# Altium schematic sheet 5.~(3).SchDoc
size 420 x 297 mm
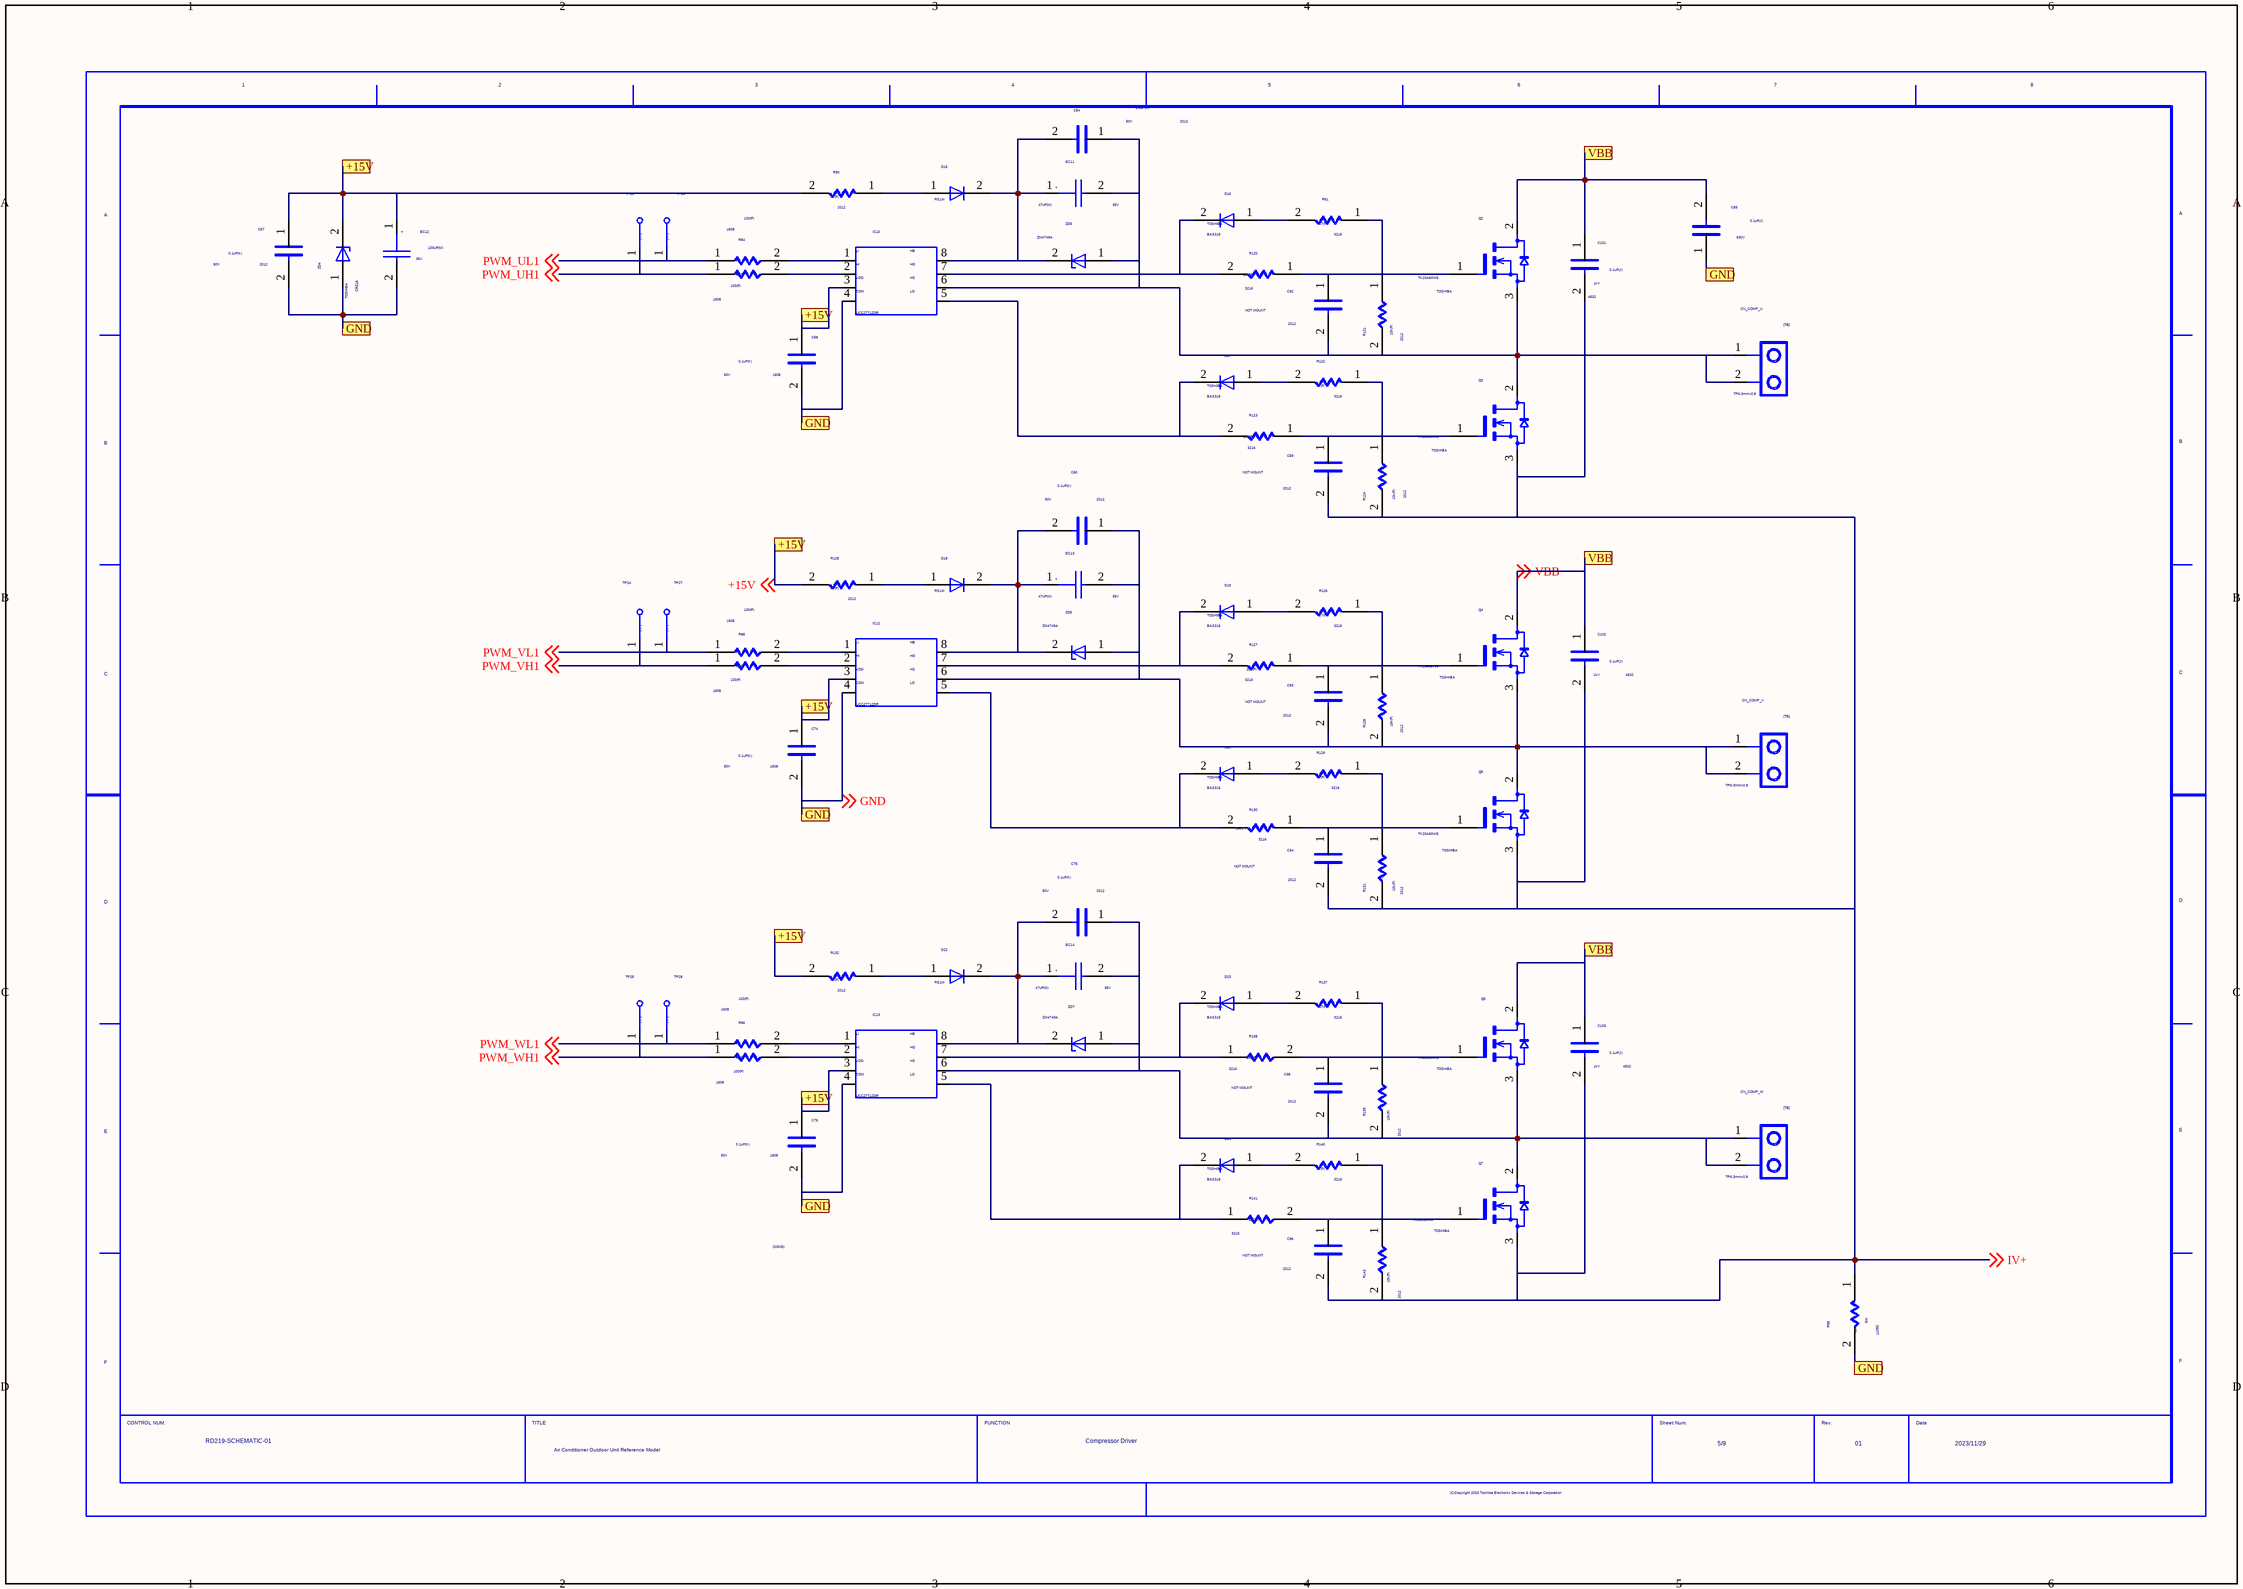
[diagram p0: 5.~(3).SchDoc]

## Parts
C54  VAL2: 50V  SIZECODESMD: 2012  VAL1: 0.1uF(K)  (hidden comment: C)
C55  VAL2: 630V  VAL1: 0.1uF(J)  (hidden comment: C)
C57  SIZECODESMD: 2012  VAL2: 50V  VAL1: 0.1uF(K)  (hidden comment: C)
C58  VAL2: 50V  SIZECODESMD: 1608  VAL1: 0.1uF(K)  (hidden comment: C)
C59  SIZECODESMD: 2012  NOTMOUNT: NOT MOUNT  (hidden comment: C)
C60  VAL2: 50V  SIZECODESMD: 2012  VAL1: 0.1uF(K)  (hidden comment: C)
C74  VAL2: 50V  SIZECODESMD: 1608  VAL1: 0.1uF(K)  (hidden comment: C)
C75  VAL2: 50V  SIZECODESMD: 2012  VAL1: 0.1uF(K)  (hidden comment: C)
C76  COMPCOMMENT: (SGND)  VAL2: 50V  SIZECODESMD: 1608  VAL1: 0.1uF(K)  (hidden comment: C)
C92  NOTMOUNT: NOT MOUNT  SIZECODESMD: 2012  (hidden comment: C)
C93  NOTMOUNT: NOT MOUNT  SIZECODESMD: 2012  (hidden comment: C)
C94  SIZECODESMD: 2012  NOTMOUNT: NOT MOUNT  (hidden comment: C)
C95  NOTMOUNT: NOT MOUNT  SIZECODESMD: 2012  (hidden comment: C)
C96  SIZECODESMD: 2012  NOTMOUNT: NOT MOUNT  (hidden comment: C)
C101  VAL2: 1kV  SIZECODESMD: 4532  VAL1: 0.1uF(J)  (hidden comment: C)
C102  VAL2: 1kV  SIZECODESMD: 4532  VAL1: 0.1uF(J)  (hidden comment: C)
C103  VAL2: 1kV  SIZECODESMD: 4532  VAL1: 0.1uF(J)  (hidden comment: C)
CN_COMP_U  COMPCOMMENT: TP6.3mmx0.8  (hidden comment: TB2A)
CN_COMP_V  COMPCOMMENT: TP6.3mmx0.8  (hidden comment: TB2A)
CN_COMP_W  COMPCOMMENT: TP6.3mmx0.8  (hidden comment: TB2A)
D15  VAL3: RS1M  (hidden comment: D_CUSTOM)
D16  USERCOMPTEXT3: TOSHIBA  VAL3: BAS316  (hidden comment: D_CUSTOM)
D17  USERCOMPTEXT3: TOSHIBA  VAL3: BAS316  (hidden comment: D_CUSTOM)
D18  VAL3: RS1M  (hidden comment: D_CUSTOM)
D19  USERCOMPTEXT3: TOSHIBA  VAL3: BAS316  (hidden comment: D_CUSTOM)
D21  USERCOMPTEXT3: TOSHIBA  VAL3: BAS316  (hidden comment: D_CUSTOM)
D22  VAL3: RS1M  (hidden comment: D_CUSTOM)
D23  USERCOMPTEXT3: TOSHIBA  VAL3: BAS316  (hidden comment: D_CUSTOM)
D24  USERCOMPTEXT3: TOSHIBA  VAL3: BAS316  (hidden comment: D_CUSTOM)
EC11  VAL2: 35V  VAL1: 47uF(M)  (hidden comment: EC)
EC12  VAL2: 35V  VAL1: 100uF(M)  (hidden comment: EC)
EC13  VAL2: 35V  VAL1: 47uF(M)  (hidden comment: EC)
EC14  VAL2: 35V  VAL1: 47uF(M)  (hidden comment: EC)
IC10  VAL3: UCC27712DR  (hidden comment: UCC27712)
IC12  VAL3: UCC27712DR  (hidden comment: UCC27712)
IC13  VAL3: UCC27712DR  (hidden comment: UCC27712)
Q2  USERCOMPTEXT3: TOSHIBA  (hidden comment: TK20A60W5)
Q3  USERCOMPTEXT3: TOSHIBA  (hidden comment: TK20A60W5)
Q4  USERCOMPTEXT3: TOSHIBA  (hidden comment: TK20A60W5)
Q5  USERCOMPTEXT3: TOSHIBA  (hidden comment: TK20A60W5)
Q6  USERCOMPTEXT3: TOSHIBA  (hidden comment: TK20A60W5)
Q7  USERCOMPTEXT3: TOSHIBA  (hidden comment: TK20A60W5)
R84  SIZECODESMD: 1608  VAL1: 100(F)  (hidden comment: R)
R85  SIZECODESMD: 1608  VAL1: 100(F)  (hidden comment: R)
R86  SIZECODESMD: 1608  VAL1: 100(F)  (hidden comment: R)
R87  SIZECODESMD: 1608  VAL1: 100(F)  (hidden comment: R)
R88  SIZECODESMD: 1608  VAL1: 100(F)  (hidden comment: R)
R89  SIZECODESMD: 1608  VAL1: 100(F)  (hidden comment: R)
R90  SIZECODESMD: 2012  VAL1: 47(F)  (hidden comment: R)
R91  SIZECODESMD: 3216  VAL1: 47(F)  (hidden comment: R)
R95  VAL2: 5W  SIZECODESMD: 11050  VAL1: 10m  (hidden comment: R)
R120  SIZECODESMD: 3216  VAL1: 200(F)  (hidden comment: R)
R121  SIZECODESMD: 2012  VAL1: 10k(F)  (hidden comment: R)
R122  SIZECODESMD: 3216  VAL1: 47(F)  (hidden comment: R)
R123  SIZECODESMD: 3216  VAL1: 200(F)  (hidden comment: R)
R124  SIZECODESMD: 2012  VAL1: 10k(F)  (hidden comment: R)
R125  SIZECODESMD: 2012  VAL1: 47(F)  (hidden comment: R)
R126  SIZECODESMD: 3216  VAL1: 47(F)  (hidden comment: R)
R127  SIZECODESMD: 3216  VAL1: 200(F)  (hidden comment: R)
R128  SIZECODESMD: 2012  VAL1: 10k(F)  (hidden comment: R)
R129  SIZECODESMD: 3216  VAL1: 47(F)  (hidden comment: R)
R130  SIZECODESMD: 3216  VAL1: 200(F)  (hidden comment: R)
R131  SIZECODESMD: 2012  VAL1: 10k(F)  (hidden comment: R)
R132  SIZECODESMD: 2012  VAL1: 47(F)  (hidden comment: R)
R137  SIZECODESMD: 3216  VAL1: 47(F)  (hidden comment: R)
R138  SIZECODESMD: 3216  VAL1: 200(F)  (hidden comment: R)
R139  SIZECODESMD: 2012  VAL1: 10k(F)  (hidden comment: R)
R140  SIZECODESMD: 3216  VAL1: 47(F)  (hidden comment: R)
R141  SIZECODESMD: 3216  VAL1: 200(J)  (hidden comment: R)
R143  SIZECODESMD: 2012  VAL1: 10k(F)  (hidden comment: R)
TP23  TP  (value not drawn)
TP24  TP  (value not drawn)
TP25  TP  (value not drawn)
TP26  TP  (value not drawn)
TP27  TP  (value not drawn)
TP28  TP  (value not drawn)
U?  DATE: 2023/11/29  FUNCTION: Compressor Driver  TITLE: Air Conditioner Outdoor Unit / Reference Model  DRAWINGNUMBER: RD219-SCHEMATIC-01  SHEETNUMBER: 5/9  REVISION: 01  (hidden comment: WAKU_DEF100)
ZD4  USERCOMPTEXT3: TOSHIBA  VAL3: CRZ18  (hidden comment: ZD_CUSTOM)
ZD5  VAL3: ZM4749A  (hidden comment: ZD_CUSTOM)
ZD6  VAL3: ZM4749A  (hidden comment: ZD_CUSTOM)
ZD7  VAL3: ZM4749A  (hidden comment: ZD_CUSTOM)

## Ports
+15V, GND, VBB

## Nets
+15V: C57.1 C58.1 C74.1 C76.1 EC12.1 IC10.3 IC12.3 IC13.3 R90.2 R125.2 R132.2 ZD4.2 ; off-sheet +15V, port +15V
GND: C55.1 C57.2 C58.2 C74.2 C76.2 EC12.2 IC10.4 IC12.4 IC13.4 R95.2 ZD4.1 ; off-sheet GND, port GND
IV+: C59.2 C94.2 C96.2 C101.2 C102.2 C103.2 Q3.3 Q5.3 Q7.3 R95.1 R124.2 R131.2 R143.2 ; off-sheet IV+
NetC54_1: C54.1 C92.2 CN_COMP_U.1 CN_COMP_U.2 EC11.2 IC10.6 Q2.3 Q3.2 R121.2 ZD5.1
NetC54_2: C54.2 D15.2 EC11.1 IC10.8 ZD5.2
NetC59_1: C59.1 Q3.1 R122.1 R123.1 R124.1
NetC60_1: C60.1 C93.2 CN_COMP_V.1 CN_COMP_V.2 EC13.2 IC12.6 Q4.3 Q5.2 R128.2 ZD6.1
NetC60_2: C60.2 D18.2 EC13.1 IC12.8 ZD6.2
NetC75_1: C75.1 C95.2 CN_COMP_W.1 CN_COMP_W.2 EC14.2 IC13.6 Q6.3 Q7.2 R139.2 ZD7.1
NetC75_2: C75.2 D22.2 EC14.1 IC13.8 ZD7.2
NetC92_1: C92.1 Q2.1 R91.1 R120.1 R121.1
NetC93_1: C93.1 Q4.1 R126.1 R127.1 R128.1
NetC94_1: C94.1 Q5.1 R129.1 R130.1 R131.1
NetC95_1: C95.1 Q6.1 R137.1 R138.2 R139.1
NetC96_1: C96.1 Q7.1 R140.1 R141.2 R143.1
NetD15_1: D15.1 R90.1
NetD16_1: D16.1 R91.2
NetD16_2: D16.2 IC10.7 R120.2
NetD17_1: D17.1 R122.2
NetD17_2: D17.2 IC10.5 R123.2
NetD18_1: D18.1 R125.1
NetD19_1: D19.1 R126.2
NetD19_2: D19.2 IC12.7 R127.2
NetD21_1: D21.1 R129.2
NetD21_2: D21.2 IC12.5 R130.2
NetD22_1: D22.1 R132.1
NetD23_1: D23.1 R137.2
NetD23_2: D23.2 IC13.7 R138.1
NetD24_1: D24.1 R140.2
NetD24_2: D24.2 IC13.5 R141.1
NetIC10_1: IC10.1 R84.2
NetIC10_2: IC10.2 R87.2
NetIC12_1: IC12.1 R85.2
NetIC12_2: IC12.2 R88.2
NetIC13_1: IC13.1 R86.2
NetIC13_2: IC13.2 R89.2
PWM_UH1: R87.1 TP23.1 ; off-sheet PWM_UH1
PWM_UL1: R84.1 TP26.1 ; off-sheet PWM_UL1
PWM_VH1: R88.1 TP24.1 ; off-sheet PWM_VH1
PWM_VL1: R85.1 TP27.1 ; off-sheet PWM_VL1
PWM_WH1: R89.1 TP25.1 ; off-sheet PWM_WH1
PWM_WL1: R86.1 TP28.1 ; off-sheet PWM_WL1
VBB: C55.2 C101.1 C102.1 C103.1 Q2.2 Q4.2 Q6.2 ; off-sheet VBB, port VBB

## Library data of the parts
C54 C60 C75 = C: OriginalSymbolOrigin: (2540,7620); COMP: AC0805KRX7R9BB104
C55 = C: OriginalSymbolOrigin: (2540,7620); COMP: CBB22_104J630V
C57 = C: OriginalSymbolOrigin: (2540,7620); VAL3: AC0805KRX7R9BB104
C58 C74 C76 = C: OriginalSymbolOrigin: (2540,7620); COMP: AC0603KRX7R9BB104
C59 C92-C96 = C: OriginalSymbolOrigin: (2540,7620); COMP: SMT_0805_C
C101-C103 = C: OriginalSymbolOrigin: (2540,7620); COMP: C1812C104JDRACTU
CN_COMP_U CN_COMP_V CN_COMP_W = TB2A: SAVEAREA0: -6249,-369,19007,18120; TIME: 11:16:32; UPDATEUSER: w20165dm; SAVECOUNT: 1; OriginalSymbolOrigin: (2540,12700); VAL3: DJ6110-6.3x0.8; COMP: TP
D15-D19 D21-D24 = D_CUSTOM: SAVEAREA0: -1668,-97,14265,7829; SAVECOUNT: 4; TIME: 14:49:55; UPDATEUSER: w20165dm; UPDATETIME: 16:47:49; OriginalSymbolOrigin: (5080,5080)
EC11 EC13 EC14 = EC: SAVEAREA0: -1432,-1528,20311,14389; SAVECOUNT: 53; TIME: 15:02:55; UPDATEUSER: w20165dm; UPDATETIME: 16:35:05; OriginalSymbolOrigin: (2540,10160); VAL3: CS1V470M_CRE54
EC12 = EC: SAVEAREA0: -1432,-1528,20311,14389; SAVECOUNT: 53; TIME: 15:02:55; UPDATEUSER: w20165dm; UPDATETIME: 16:35:05; OriginalSymbolOrigin: (2540,10160); VAL3: CS1V101M_CRE77
IC10 IC12 IC13 = UCC27712: COMPTYPERIPPER: Y; TIME: 09:28:59; UPDATEUSER: sptcae13; UPDATETIME: 09:18:42; SAVECOUNT: 4; SAVEAREA0: -15749,-25534,36467,12691; OriginalSymbolOrigin: (2540,0)
Q2-Q7 = TK20A60W5: SAVECOUNT: 12; SAVEAREA0: -8472,-176,23454,15707; TIME: 13:50:47; UPDATEUSER: w20165dm; OriginalSymbolOrigin: (5080,12700)
R84-R89 = R: OriginalSymbolOrigin: (5080,5080); COMP: AC0603FR_07100RL; VAL2: 100mW
R90 R125 R132 = R: OriginalSymbolOrigin: (5080,5080); COMP: AC0805FR_0747RL; VAL2: 125mW
R91 R122 R126 R129 R137 R140 = R: OriginalSymbolOrigin: (5080,5080); COMP: AC1206FR_0747RL; VAL2: 250mW
R95 = R: OriginalSymbolOrigin: (5080,5080); COMP: FCSL110R010FER
R120 R123 R127 R130 R138 R141 = R: OriginalSymbolOrigin: (5080,5080); COMP: AC1206FR_07200RL; VAL2: 250mW
R121 R124 R128 R131 R139 R143 = R: OriginalSymbolOrigin: (5080,5080); COMP: AC08005FR_0710KL; VAL3: AC0805FR_0710KL; VAL2: 125mW
TP23 = TP_Dup1: TIME: 16:12:21; UPDATEUSER: fukuda-y; UPDATETIME: 16:18:11; SAVECOUNT: 2; SAVEAREA0: -242,-92,12810,7836; OriginalSymbolOrigin: (0,7620); COMPCOMMENT: UH1; VAL3: ZXD
TP24 = TP_Dup1: TIME: 16:12:21; UPDATEUSER: fukuda-y; UPDATETIME: 16:18:11; SAVECOUNT: 2; SAVEAREA0: -242,-92,12810,7836; OriginalSymbolOrigin: (0,7620); COMPCOMMENT: VH1; VAL3: ZXD
TP25 = TP_Dup1: TIME: 16:12:21; UPDATEUSER: fukuda-y; UPDATETIME: 16:18:11; SAVECOUNT: 2; SAVEAREA0: -242,-92,12810,7836; OriginalSymbolOrigin: (0,7620); COMPCOMMENT: WH1; VAL3: ZXD
TP26 = TP_Dup1: TIME: 16:12:21; UPDATEUSER: fukuda-y; UPDATETIME: 16:18:11; SAVECOUNT: 2; SAVEAREA0: -242,-92,12810,7836; OriginalSymbolOrigin: (0,7620); COMPCOMMENT: UL1; VAL3: ZXD
TP27 = TP_Dup1: TIME: 16:12:21; UPDATEUSER: fukuda-y; UPDATETIME: 16:18:11; SAVECOUNT: 2; SAVEAREA0: -242,-92,12810,7836; OriginalSymbolOrigin: (0,7620); COMPCOMMENT: VL1; VAL3: ZXD
TP28 = TP_Dup1: TIME: 16:12:21; UPDATEUSER: fukuda-y; UPDATETIME: 16:18:11; SAVECOUNT: 2; SAVEAREA0: -242,-92,12810,7836; OriginalSymbolOrigin: (0,7620); COMPCOMMENT: WL1; VAL3: ZXD
U? = WAKU_DEF100: PLOTTIME: HH:MM; SAVEAREA0: -45080,-4508,463680,304612; TIME: 10:14:29; UPDATEUSER: sptcae13; UPDATETIME: 08:19:30; SAVECOUNT: 8; OriginalSymbolOrigin: (10160,284480)
ZD4 = ZD_CUSTOM: SAVEAREA0: -4071,-115,16804,10270; TIME: 09:43:08; UPDATEUSER: w20165dm; UPDATETIME: 16:32:57; SAVECOUNT: 4; OriginalSymbolOrigin: (5080,5080)
ZD5-ZD7 = ZD_CUSTOM: SAVEAREA0: -4071,-115,16804,10270; TIME: 09:43:08; UPDATEUSER: w20165dm; UPDATETIME: 16:32:57; SAVECOUNT: 4; OriginalSymbolOrigin: (5080,5080); VAL2: 1W; VAL1: 24V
